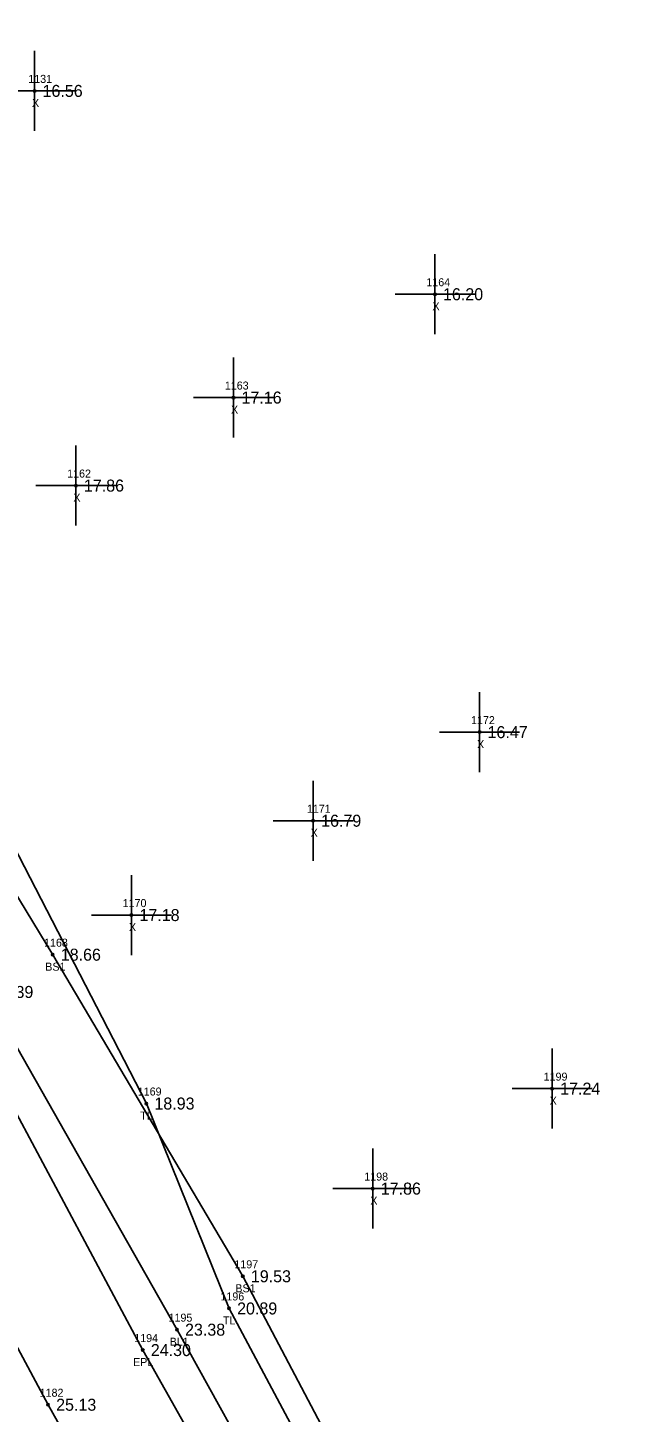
# Model space of a CAD drawing. Extents: x 2042211 to 2045853, y 303080 to 309569.
# Drawn here: x 2043073.7 to 2043149.9, y 306428.3 to 306601.3 of the extents above; entities that cross this region are included whole.
import ezdxf

# ---------------------------------------------------------------- set-up
doc = ezdxf.new("R2010")
doc.units = 0
for name, color, linetype in [('BR_500YR_SCOUR', 7, 'Continuous'), ('RD_DTM_BkLn1', 7, 'Continuous'), ('RD_DTM_BkLn2', 7, 'Continuous'), ('RD_DTM_BkLn_txCode', 7, 'Continuous'), ('RD_EX_Misc', 7, 'Continuous'), ('RD_EX_Misc_txCode', 7, 'Continuous'), ('RD_EX_Road', 7, 'Continuous'), ('RD_EX_Road_txCode', 7, 'Continuous'), ('RD_EX_TX_Misc_ELEV', 7, 'Continuous'), ('RD_EX_TX_Road_ELEV', 7, 'Continuous'), ('RD_EX_TX_VEG_ELEV', 7, 'Continuous'), ('RD_EX_VEG_txCode', 7, 'Continuous'), ('RD_HC_Survey_ELEV', 7, 'Continuous'), ('RD_HC_Survey_txCode', 7, 'Continuous'), ('RD_SMD_Locator', 7, 'Continuous')]:
    doc.layers.add(name, color=color, linetype=linetype)

msp = doc.modelspace()

# ---------------------------------------------------------------- linework, layer by layer
at = {"layer": 'BR_500YR_SCOUR'}
msp.add_lwpolyline([(2043030.11, 306588.1), (2043035.72, 306574.19), (2043060.12, 306522.02), (2043088.59, 306466.9), (2043098.93, 306441.29), (2043120.97, 306400.06), (2043177.31, 306317.21), (2043201.76, 306279.58), (2043229.83, 306237.41), (2043260.65, 306197.8), (2043289.37, 306160.32), (2043322.23, 306122.17), (2043376.5, 306058.9), (2043456.79, 305961.76), (2043477.52, 305946.76)], dxfattribs=at)
for centre in [(2043088.59, 306466.9), (2043098.93, 306441.29)]:
    msp.add_circle(centre, 0.15, dxfattribs=at)
at = {"layer": 'RD_DTM_BkLn1'}
for points in [[(2042839.81, 307329.37), (2042840.93, 307280.46), (2042843.39, 307231.17), (2042846.87, 307181.66), (2042851.76, 307132.07), (2042857.83, 307083.36), (2042865.03, 307034.36), (2042873.56, 306985.67), (2042883.71, 306937.59), (2042895.32, 306889.27), (2042908.01, 306841.41), (2042921.81, 306793.88), (2042936.83, 306746.34), (2042953.05, 306699.55), (2042970.36, 306653.6), (2042989.25, 306607.34), (2043009.36, 306561.99), (2043030.44, 306517.39), (2043052.89, 306472.91), (2043076.3, 306429.26), (2043100.43, 306386.21)], [(2042857.66, 307329.64), (2042861.09, 307281.84), (2042862.27, 307232.19), (2042866.29, 307183.84), (2042870.56, 307134.28), (2042875.48, 307086.26), (2042882.95, 307037.68), (2042891.21, 306988.93), (2042900.82, 306941.19), (2042911.81, 306893.75), (2042924.4, 306846), (2042938.51, 306799.29), (2042953.5, 306752.33), (2042968.09, 306705.62), (2042985.63, 306659.36), (2043004.49, 306613.62), (2043024.61, 306569.26), (2043045.97, 306525.25), (2043068.43, 306480.84), (2043092.42, 306438.64), (2043116.55, 306395.12)]]:
    msp.add_lwpolyline(points, dxfattribs=at)
at = {"layer": 'RD_DTM_BkLn2'}
msp.add_lwpolyline([(2043050.77, 306528.53), (2043076.88, 306485.5), (2043100.65, 306445.31), (2043124.7, 306399.73), (2043150.39, 306358.68), (2043176.89, 306319.64), (2043207.15, 306280.1), (2043235.9, 306243.12), (2043269.2, 306203.58), (2043298.35, 306167.99), (2043333.27, 306134.3), (2043400.8, 306058.89), (2043462.45, 305984.07), (2043465.98, 305983.25), (2043477.77, 305989.95), (2043480.51, 305990.34), (2043485.87, 305978.76), (2043487.92, 305969.11), (2043488.21, 305955.35)], dxfattribs=at)
at = {"layer": 'RD_EX_Misc'}
for p, q in [((2043074.6, 306588.44), (2043074.6, 306598.44)), ((2043069.6, 306593.44), (2043079.6, 306593.44)), ((2043124.68, 306563.03), (2043124.68, 306573.03)), ((2043119.68, 306568.03), (2043129.68, 306568.03)), ((2043099.48, 306550.12), (2043099.48, 306560.12)), ((2043094.48, 306555.12), (2043104.48, 306555.12)), ((2043079.77, 306539.12), (2043079.77, 306549.12)), ((2043074.77, 306544.12), (2043084.77, 306544.12)), ((2043130.25, 306508.31), (2043130.25, 306518.31)), ((2043125.25, 306513.31), (2043135.25, 306513.31)), ((2043109.44, 306497.24), (2043109.44, 306507.24)), ((2043104.44, 306502.24), (2043114.44, 306502.24)), ((2043086.72, 306485.45), (2043086.72, 306495.45)), ((2043081.72, 306490.45), (2043091.72, 306490.45)), ((2043139.33, 306463.76), (2043139.33, 306473.76)), ((2043134.33, 306468.76), (2043144.33, 306468.76)), ((2043116.9, 306451.27), (2043116.9, 306461.27)), ((2043111.9, 306456.27), (2043121.9, 306456.27))]:
    msp.add_line(p, q, dxfattribs=at)
at = {"layer": 'RD_EX_Road'}
msp.add_lwpolyline([(2042853.31, 307329.44), (2042854.43, 307281.38), (2042857.15, 307232.07), (2042860.27, 307183.35), (2042865.16, 307133.89), (2042871.37, 307085.7), (2042878.53, 307037.13), (2042886.97, 306988.21), (2042897.02, 306940.01), (2042908.28, 306892.66), (2042921.09, 306844.85), (2042934.41, 306798.2), (2042949.37, 306750.96), (2042965.62, 306704.44), (2042983.48, 306658.43), (2043001.91, 306612.18), (2043021.64, 306567.98), (2043042.58, 306523.81), (2043065.05, 306479.23), (2043088.14, 306436.09), (2043112.53, 306392.81)], dxfattribs=at)
at = {"layer": 'RD_SMD_Locator'}
for centre in [(2043074.6, 306593.44), (2043124.68, 306568.03), (2043099.48, 306555.12), (2043079.77, 306544.12), (2043130.25, 306513.31), (2043109.44, 306502.24), (2043086.72, 306490.45), (2043076.88, 306485.5), (2043139.33, 306468.76), (2043116.9, 306456.27), (2043100.65, 306445.31), (2043092.42, 306438.64), (2043088.14, 306436.09), (2043076.3, 306429.26)]:
    msp.add_circle(centre, 0.15, dxfattribs=at)

# ---------------------------------------------------------------- texts
at = {"layer": 'RD_DTM_BkLn_txCode'}
for s, p in [('1168', (2043075.79, 306486.5)), ('BS1', (2043075.94, 306483.5)), ('1197', (2043099.59, 306446.31)), ('BS1', (2043099.71, 306443.31)), ('1195', (2043091.36, 306439.64)), ('BL1', (2043091.5, 306436.64))]:
    msp.add_text(s, height=1, dxfattribs=at).set_placement(p)
at = {"layer": 'RD_EX_Misc_txCode'}
for s, p in [('1131', (2043073.82, 306594.44)), ('X', (2043074.28, 306591.44)), ('1164', (2043123.6, 306569.03)), ('X', (2043124.37, 306566.03)), ('1163', (2043098.4, 306556.12)), ('X', (2043099.17, 306553.12)), ('1162', (2043078.68, 306545.12)), ('X', (2043079.45, 306542.12)), ('1172', (2043129.19, 306514.31)), ('X', (2043129.94, 306511.31)), ('1171', (2043108.66, 306503.24)), ('X', (2043109.13, 306500.24)), ('1170', (2043085.62, 306491.45)), ('X', (2043086.41, 306488.45)), ('1199', (2043138.27, 306469.76)), ('X', (2043139.02, 306466.76)), ('1198', (2043115.84, 306457.27)), ('X', (2043116.59, 306454.27))]:
    msp.add_text(s, height=1, dxfattribs=at).set_placement(p)
at = {"layer": 'RD_EX_Road_txCode'}
for s, p in [('1194', (2043087.07, 306437.09)), ('EPL', (2043086.93, 306434.09))]:
    msp.add_text(s, height=1, dxfattribs=at).set_placement(p)
at = {"layer": 'RD_EX_TX_Misc_ELEV'}
for s, p in [('16.56', (2043075.6, 306592.69)), ('16.20', (2043125.68, 306567.28)), ('17.16', (2043100.48, 306554.37)), ('17.86', (2043080.77, 306543.37)), ('16.47', (2043131.25, 306512.56)), ('16.79', (2043110.44, 306501.49)), ('17.18', (2043087.72, 306489.7)), ('18.66', (2043077.88, 306484.75)), ('22.39', (2043069.43, 306480.09)), ('17.24', (2043140.33, 306468.01)), ('17.86', (2043117.9, 306455.52)), ('19.53', (2043101.65, 306444.56)), ('23.38', (2043093.42, 306437.89))]:
    msp.add_text(s, height=1.5, dxfattribs=at).set_placement(p)
at = {"layer": 'RD_EX_TX_Road_ELEV'}
msp.add_text('24.30', height=1.5, dxfattribs=at).set_placement((2043089.14, 306435.34))
at = {"layer": 'RD_EX_TX_VEG_ELEV'}
for s, p in [('18.93', (2043089.59, 306466.15)), ('20.89', (2043099.93, 306440.54))]:
    msp.add_text(s, height=1.5, dxfattribs=at).set_placement(p)
at = {"layer": 'RD_EX_VEG_txCode'}
for s, p in [('1169', (2043087.51, 306467.9)), ('TL', (2043087.82, 306464.9)), ('1196', (2043097.85, 306442.29)), ('TL', (2043098.16, 306439.29))]:
    msp.add_text(s, height=1, dxfattribs=at).set_placement(p)
at = {"layer": 'RD_HC_Survey_ELEV'}
msp.add_text('25.13', height=1.5, dxfattribs=at).set_placement((2043077.3, 306428.51))
at = {"layer": 'RD_HC_Survey_txCode'}
msp.add_text('1182', height=1, dxfattribs=at).set_placement((2043075.24, 306430.26))

doc.saveas('drawing.dxf')
